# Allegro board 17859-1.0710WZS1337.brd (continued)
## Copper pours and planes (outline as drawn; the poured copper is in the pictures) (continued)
3D3V_S5_KBC on L3: 27.96,55.15 28.49,55.15 28.67,54.97 28.67,54.64 28.38,54.35 28.38,51.83 27.44,50.89 27.21,50.89 26.82,51.29 26.82,53.06 27.71,53.95 27.71,54.89
3D3V_S5_PCH on TOP: 145.99,77.63 145.79,77.83 145.79,79.94 145.82,79.96 146.91,79.96 147.14,79.73 147.14,78.29 146.48,77.63
3D3V_S5_PCH on TOP: 144.37,71.58 143.68,72.27 137.87,72.27 137.85,72.28 137.29,72.28 136.7,72.88 136.7,73.54 136.95,73.79 137.81,73.79 138.02,73.59 141.65,73.59 142.21,73.03 143.99,73.03 144.16,72.85 145.61,72.85 145.79,72.67 145.79,71.73 145.64,71.58
3D3V_S5_PCH on BOTTOM: 134.72,70.18 134.69,70.21 134.69,70.92 134.82,71.05 134.82,73.79 134.89,73.87 135.71,73.87 136.06,74.22 136.06,74.37 136.11,74.42 136.57,74.42 136.62,74.37 136.62,73.79 136.75,73.66 137.36,73.66 137.41,73.61 137.41,73.31 137.23,73.13 136.27,73.13 135.99,72.85 135.99,70.67 135.5,70.18 ; 1 cut-out
3D3V_SPIVCC1 on TOP: 187.83,35.33 187.67,35.49 187.67,37.65 187.55,37.77 186.43,37.77 186.2,37.54 184.65,37.54 184.58,37.62 184.58,39.04 184.73,39.19 188.74,39.19 188.75,39.18 189.19,39.18 189.38,38.99 189.38,37.72 189.22,37.57 188.79,37.57 188.72,37.49 188.72,36.91 188.69,36.88 188.69,35.69 188.34,35.33 ; 3 cut-outs
3D3V_SSD on TOP: 216.2,18.57 216.05,18.72 216.05,21.9 216.45,22.3 221.25,22.3 221.43,22.13 221.43,18.82 221.18,18.57 ; 6 cut-outs
3D3V_SSD on TOP: 217.01,2.92 215.39,4.55 215.39,7.01 215.61,7.24 217.85,7.24 218.21,6.89 218.21,5.62 218.48,5.34 219.35,5.34 219.58,5.11 219.58,3.25 219.25,2.92 ; 5 cut-outs
3D3V_SSD on BOTTOM: 216.99,2.95 216.02,3.91 216.02,5.31 216.07,5.36 217.77,5.36 218.59,6.17 218.59,6.63 219.32,7.37 219.32,16.82 218.1,18.04 216.1,18.04 216.02,18.11 216.02,19.81 216.05,19.84 217.82,19.84 218.03,20.04 218.03,21.41 217.88,21.57 216.1,21.57 216.02,21.64 216.02,22.66 216.1,22.74 221.38,22.74 222.78,21.34 222.78,7.11 222.02,6.35 222.02,4.32 220.64,2.95
3D3V_TP_VDD on TOP: 176.17,3.89 175.58,4.47 175.58,8.13 175.64,8.18 176.88,8.18 176.96,8.11 176.96,7.11 177.26,6.81 177.26,5.62 177.46,5.41 179.27,5.41 179.65,5.79 179.65,7.29 179.55,7.39 178.45,7.39 178.2,7.65 178.2,9.3 178.38,9.48 180.89,9.48 180.97,9.4 180.97,8.49 180.89,8.41 180.33,8.41 180.21,8.28 180.21,7.52 180.41,7.32 181.12,7.32 181.38,7.06 181.38,4.68 180.59,3.89 ; 7 cut-outs
3D3V_TPAN_VDD on TOP: 57.75,90.02 57.42,90.35 57.42,92.83 57.55,92.96 61.58,92.96 61.76,92.77 61.77,92.77 61.77,90.25 61.54,90.02 ; 4 cut-outs
3D3V_VCCPRIM on TOP: 118.13,70.59 118.13,71.96 118.23,72.06 118.59,72.06 118.66,71.99 118.66,71.53 118.99,71.2 120.09,71.2 120.75,70.54 121.89,70.54 122.02,70.67 122.02,71.02 122.68,71.68 122.68,72.82 122.45,73.05 122.45,73.69 122.16,73.98 121.34,73.98 121.23,74.09 121.23,74.42 121.38,74.58 124.02,74.58 124.12,74.48 124.12,74.02 123.23,73.13 123.23,72.29 123.36,72.16 123.74,72.16 123.92,71.99 123.92,70.36 123.26,69.7 119.5,69.7 119.42,69.78 119.42,70.31 119.25,70.49 118.23,70.49 ; 2 cut-outs
3D3V_VCCPRIM on TOP: 145.66,81.71 145.59,81.79 145.59,86.18 145.46,86.31 145.46,88.72 145.71,88.98 146.48,88.98 146.6,88.85 146.6,87.71 147.36,86.95 147.36,82.48 147.52,82.32 147.52,81.87 147.36,81.71 ; 9 cut-outs
3D3V_VCCPRIM on BOTTOM: 122.4,70.26 122.3,70.36 122.3,71.25 122.55,71.5 123.97,71.5 124.07,71.4 124.07,70.39 123.95,70.26
3D3V_VCCPRIM on L3: 130.18,68.85 130.5,68.53 135.33,68.53 136.47,67.39 142.79,67.39 144.11,66.07 146.43,66.07 146.58,65.92 146.58,64.42 146.12,63.96 142.62,63.96 141.85,64.72 133.57,64.72 132.58,63.73 129.46,63.73 127.45,65.74 127.45,67.01 126.69,67.77 126.69,68.38 126.52,68.54 123.27,68.54 122.31,69.51 119.73,69.51 119.42,69.81 119.42,70.23 119.25,70.41 118.36,70.41 118.05,70.72 118.05,71.96 118.13,72.04 118.56,72.04 118.64,71.96 118.64,71.63 118.82,71.45 119.96,71.45 120.82,70.59 121.91,70.59 122.78,71.45 128.42,71.45 130.18,69.69
3D3V_WLAN on TOP: 213.15,49.35 212.01,50.5 212.01,53.55 212.52,54.05 212.52,55.45 212.64,55.58 213.02,55.58 214.01,54.59 214.8,54.59 214.93,54.46 214.93,52.17 214.7,51.95 214.14,51.95 213.68,51.49 213.68,49.43 213.61,49.35 ; 5 cut-outs
3D3V_WLAN on BOTTOM: 202.84,48.59 202.2,49.23 201.85,49.23 201.35,48.73 200.95,48.73 199.69,49.99 196.34,49.99 194.66,51.67 194.66,54.31 194.91,54.56 195.55,54.56 195.6,54.51 195.6,52.89 195.65,52.83 195.75,52.83 195.8,52.89 195.8,54.51 195.85,54.56 196.06,54.56 196.16,54.46 196.16,52.71 196.36,52.5 199.71,52.5 200.35,51.87 203.85,51.87 204.46,51.26 206.57,51.26 207.66,52.35 208.78,52.35 209.37,51.77 211.83,51.77 212.8,52.73 212.8,54.49 212.82,54.51 213.05,54.51 213.1,54.46 213.1,52.91 213.15,52.86 213.28,52.86 213.3,52.89 213.3,54.46 213.35,54.51 213.79,54.51 214.55,53.75 214.55,52.12 212.52,50.09 207.77,50.09 206.27,48.59
+DC_IN on TOP: 31.64,86.79 31.54,86.9 31.54,87.99 31.19,88.34 30.52,88.34 30.47,88.29 29.2,88.29 29.05,88.45 29.05,88.93 28.85,89.13 27.96,89.13 27.78,89.31 27.78,90.33 27.88,90.43 32.23,90.43 33.62,89.03 35,89.03 35.2,88.83 35.2,87.12 34.87,86.79 ; 3 cut-outs
+DC_IN_C on TOP: 28.26,90.73 28.24,90.76 28.24,94.39 28.62,94.77 32.4,94.77 32.91,94.26 32.91,91.8 32.61,91.49 32.61,90.99 32.35,90.73 ; 3 cut-outs
+DC_IN_C on BOTTOM: 29.69,86.72 29.64,86.77 29.64,87.76 29.51,87.89 28.49,87.89 28.39,87.99 28.39,92.56 28.75,92.92 32.05,92.92 32.28,92.69 32.28,89.13 32.05,88.9 32.05,86.9 31.87,86.72 ; 1 cut-out
+SDC_IN on TOP: 24.58,84.58 24.48,84.69 24.48,86.26 24.56,86.34 25.19,86.34 25.29,86.44 25.29,87.56 25.11,87.73 21.66,87.73 21.53,87.86 21.53,88.34 21.42,88.46 19.39,88.46 18.99,88.85 16.81,88.85 15.95,87.99 15.95,87.15 15.69,86.9 14.8,86.9 14.65,86.74 13.81,86.74 13.63,86.92 13.63,87.61 14.78,88.75 14.78,90.88 16.02,92.13 16.33,92.13 16.63,92.43 16.63,93.2 16.89,93.45 19.48,93.45 19.98,92.94 22.42,92.94 22.93,92.43 22.93,92.13 23.79,91.26 26.05,91.26 27.55,89.77 27.55,87.07 27.1,86.62 27.1,84.71 26.97,84.58 ; 2 cut-outs
+SDC_IN on BOTTOM: 149.14,13.16 148.89,13.41 148.89,16.59 148.63,16.84 148.63,17.35 148.83,17.54 151.64,17.54 151.75,17.44 151.75,14.82 151.1,14.18 151.1,13.29 150.97,13.16
+SDC_IN on BOTTOM: 24.96,84.61 24.73,84.84 24.73,86.69 25.72,87.68 26.69,87.68 26.89,87.48 26.89,87.1 26.31,86.52 26.31,84.89 26.03,84.61 ; 2 cut-outs
+SDC_IN on L3: 25.44,27.54 28.9,27.54 29.36,27.08 29.36,23.19 29.34,23.18 32,20.53 32,20.5 32.15,20.35 36.7,20.35 39.75,17.3 39.75,14.86 38.27,13.39 31.95,13.39 28.7,16.64 28.7,19.54 25.89,22.34 25.89,23.03 25.17,23.75 24.58,23.75 23.65,24.68 23.57,24.68 21.62,26.62 13.63,26.62 13.38,26.88 13.38,38.64 13.05,38.97 13.05,54.43 14.55,55.93 14.55,61.42 13.89,62.08 13.89,65.89 12.72,67.06 12.72,80.72 13.43,81.44 13.43,82.68 13.84,83.09 13.84,83.98 13.1,84.71 13.1,91.16 13.66,91.72 16.25,91.72 16.89,92.36 16.89,93.27 17.09,93.47 18.33,93.47 18.89,92.92 18.89,91.09 18.08,90.27 18.08,89.23 17.29,88.45 17.29,86.62 17.11,86.44 17.11,79.73 16.12,78.74 16.12,74.78 17.98,72.93 17.98,65.74 18.59,65.13 18.59,53.06 17.65,52.12 17.65,42.14 17.14,41.63 17.14,40.44 18.46,39.12 18.46,35.05 21,32.51 21,30.69 21.23,30.46 22.52,30.46 ; 3 cut-outs
+SDC_IN on L4: 39.67,17.33 45.49,17.33 47.52,15.29 47.52,6.12 49.8,3.84 50.51,3.84 51.38,4.7 57.19,4.7 57.68,5.18 59.25,5.18 60.6,3.84 93.57,3.84 95.5,5.77 95.5,7.27 95.88,7.65 97.83,7.65 98.11,7.37 98.11,3.71 95.63,1.22 47.42,1.22 44.75,3.89 44.75,10.11 43.81,11.05 41.47,11.05 37.46,15.06 37.46,18.04 37.71,18.29 38.7,18.29
+SDC_IN on L4: 19.5,93.09 20.95,93.09 21.94,94.08 25.55,94.08 26.89,92.74 26.89,85.73 26.46,85.3 24.51,85.3 22.92,86.88 22.92,88.05 21.46,89.51 21.46,91.21 21.08,91.6 18.23,91.6 18,91.82 18,93.32 18.13,93.45 19.15,93.45
+SDC_IN on L6: 146.7,17.88 150.79,17.88 151.61,17.07 151.61,17.05 152.01,16.64 152.01,14.96 151.35,14.3 139.9,14.3 139.49,13.9 128.19,13.9 126.54,12.25 98.57,12.25 98.57,12.19 96.64,10.26 96.64,6.35 96.36,6.07 95.78,6.07 91.76,10.09 81.1,10.09 80.21,10.98 75.34,10.98 74.47,11.85 72.6,11.85 72.03,11.28 65.58,11.28 64.48,12.37 62.17,12.37 60.24,14.3 58.92,14.3 58.34,13.72 56.86,13.72 56.33,14.25 56.33,18.95 55.81,19.47 32.03,19.47 28.28,23.22 28.28,25.35 27.93,25.7 27.93,27.36 28.16,27.59 28.95,27.59 29.08,27.46 29.08,25.94 29.38,25.63 29.38,23.68 32.56,20.5 58.67,20.5 60.22,18.95 60.22,17.05 61.03,16.23 68.83,16.23 69.18,16.59 75.89,16.59 75.91,16.61 76.35,16.18 88.28,16.18 89.17,17.07 96.49,17.07 97.05,17.63 126.44,17.63 127.04,17.02 137.59,17.02 138.63,18.06 146.53,18.06
AD+ on TOP: 33.5,82.53 32.61,83.42 27.76,83.42 27.6,83.57 27.6,86.69 27.71,86.79 30.02,86.79 30.55,86.26 33.52,86.26 33.78,86.52 35.33,86.52 35.58,86.26 38.12,86.26 38.2,86.34 39.31,86.34 39.39,86.26 39.39,83.47 39.29,83.37 38.81,83.37 37.97,82.53 ; 6 cut-outs
AD_OFF_R on TOP: 30.37,86.79 30.19,86.97 27.98,86.97 27.68,87.28 27.68,88.72 27.78,88.83 28.7,88.83 28.85,88.67 28.85,88.27 28.98,88.14 30.52,88.14 30.6,88.22 31.06,88.22 31.29,87.99 31.29,86.85 31.24,86.79
AUD_AGND on L2GND: outline of 91 points within 1.37,0.51 26.98,24.07
AUD_AGND on L7GND: outline of 92 points within 1.37,0.51 26.98,24.07
AUD_RING on TOP: 14.7,3.48 14.52,3.66 14.52,4.52 14.62,4.63 15.26,4.63 15.49,4.4 16.2,4.4 16.44,4.16 16.44,3.67 16.25,3.48
AUD_RING on L3: 21.79,20.7 22.85,19.64 24.61,19.64 24.78,19.81 25.5,19.81 25.65,19.66 25.65,18.21 25.5,18.06 19.76,18.06 18.28,19.54 17.16,19.54 16.68,20.02 16.68,21.16 17.05,21.53 18.32,21.53 19.15,20.7
AUD_RING on L6: 18.36,19.66 17.96,19.27 17.96,18.18 16.81,17.02 16.81,16.21 16.45,15.85 16.45,14.68 16,14.23 16,11.97 16.02,11.94 16.02,11.89 14.6,10.47 14.6,7.27 14.19,6.86 14.19,6.38 14.68,5.9 14.68,4.68 15.06,4.3 16.2,4.3 16.4,4.09 16.4,3.69 15.89,3.18 15.89,3.08 13.96,3.08 13.46,3.58 13.46,5.26 13.08,5.64 13.08,11.41 15.01,13.34 15.01,15.01 15.28,15.29 15.28,15.83 15.13,15.98 15.13,16.54 15.62,17.02 15.79,17.02 16.66,17.88 16.66,20.96 16.96,21.26 17.67,21.26 18.36,20.58
AUD_SLEEVE on BOTTOM: 14.68,11.28 14.4,11.56 14.4,12.37 15.01,12.98 15.01,14.2 15.21,14.4 16.48,14.4 16.63,14.25 16.63,13.77 16.4,13.54 16.4,11.76 15.92,11.28 ; 3 cut-outs
AUD_SLEEVE on BOTTOM: 15.87,18.42 15.26,19.03 15.26,19.66 15.39,19.79 15.97,19.79 16.55,19.21 17.32,19.21 17.37,19.15 17.37,18.62 17.16,18.42
AUD_SLEEVE on L3: 15.28,19.76 15.41,19.89 16.1,19.89 17.14,18.85 17.14,16.44 16.5,15.8 16.5,14.53 16.66,14.38 16.66,13.67 16.48,13.49 15.92,13.49 15.65,13.76 15.65,16.96 16.17,17.48 16.17,17.99 15.28,18.87
AUD_SLEEVE on L4: 16.5,19.84 17.77,21.11 19.27,21.11 19.73,21.57 24.96,21.57 25.29,21.24 25.29,19.31 24.33,19.31 24,19.64 19.83,19.64 19.4,19.21 18.79,19.21 18.03,18.44 15.69,18.44 15.36,18.77 15.36,19.66 15.54,19.84 15.69,19.84 15.7,19.83 16.48,19.83 16.49,19.84
AUD_SPK_L+ on TOP: 22.3,3.33 22.17,3.46 22.17,3.94 22.27,4.04 22.27,5.18 21.81,5.64 21.81,6.28 21.91,6.38 22.88,6.38 22.93,6.33 22.93,3.53 22.73,3.33
AUD_SPK_L- on TOP: 23.57,3.38 23.06,3.89 23.06,5.39 23.41,5.74 23.41,6.25 23.54,6.38 24.45,6.38 24.56,6.28 24.56,5.64 24.3,5.39 23.95,5.39 23.64,5.08 23.64,4.5 24.2,3.94 24.2,3.53 24.05,3.38
AUD_SPK_R+ on TOP: 26.77,3.46 26.47,3.75 26.47,3.95 26.08,4.35 26.08,5.44 26.33,5.69 26.33,6.35 26.38,6.4 27.35,6.4 27.48,6.28 27.48,5.62 27.27,5.41 26.89,5.41 26.71,5.24 26.71,4.7 27.43,3.99 27.43,3.63 27.25,3.46
AUD_SPK_R- on TOP: 25.55,3.41 25.22,3.74 25.22,5.26 24.89,5.59 24.89,6.28 24.96,6.35 25.8,6.35 25.9,6.25 25.9,5.51 25.85,5.46 25.85,4.4 26.11,4.14 26.11,3.53 25.98,3.41
BT+ on TOP: 120.19,5.16 119.42,5.92 119.42,11.76 118.41,12.78 118.41,14.68 119.07,15.34 123.08,15.34 123.49,14.94 123.49,13.79 122.85,13.16 122.85,9.63 123.77,8.71 127.04,8.71 127.17,8.59 127.17,5.67 126.66,5.16 ; 5 cut-outs
BT+ on BOTTOM: 120.82,13.54 120.06,14.3 120.06,15.19 120.34,15.47 122.04,15.47 122.24,15.67 122.24,17.78 122.45,17.99 125.9,17.99 126.03,17.86 126.03,15.32 124.25,13.54
DCBATOUT on TOP: 128.49,104.42 128.34,104.57 128.34,104.93 127.93,105.34 123.84,105.34 123.54,105.64 122.37,105.64 122.07,105.34 120.34,105.34 120.09,105.59 120.09,106.28 120.72,106.91 126.66,106.91 127.65,107.9 133.95,107.9 134.08,107.77 134.08,105.57 133.78,105.26 133.78,104.5 133.7,104.42 ; 8 cut-outs
DCBATOUT on TOP: outline of 93 points within 50.71,1.68 153.16,18.09 ; 19 cut-outs
DCBATOUT on TOP: 127.2,91.44 125.83,92.81 125.83,94.64 125.98,94.8 128.26,94.8 128.57,94.49 133.67,94.49 133.69,94.48 134.65,94.48 134.72,94.41 134.72,93.86 134.53,93.67 133.74,93.67 133.42,93.35 133.42,92.43 132.43,91.44 ; 2 cut-outs
DCBATOUT on TOP: 44.7,58.4 44.62,58.47 44.62,59.18 43.99,59.82 43.99,63.45 44.37,63.83 44.37,66.42 44.65,66.7 44.65,68.61 43.22,70.03 43.22,76.56 43.4,76.74 43.4,77.6 44.29,78.49 44.29,79.56 43.89,79.96 43.89,85.12 42.39,86.62 42.39,89.46 41.27,90.58 41.27,92.28 42.59,93.6 42.59,95.33 41.83,96.09 41.83,99.26 42.89,100.33 62.65,100.33 65.24,102.91 66.42,102.91 66.45,102.95 68.92,102.95 69.44,102.43 69.44,101.91 68.93,101.4 68.93,100.99 68.83,100.89 68.83,100.49 68.37,100.03 66.16,100.03 64.01,97.87 48.74,97.87 48.61,98 46.45,98 46.27,97.82 46.27,96.73 47.31,95.68 47.33,95.68 47.33,91.77 48.03,91.07 48.03,81.77 49.42,80.37 49.42,76.53 49.32,76.43 47.29,76.43 46.58,77.14 45.84,77.14 44.8,76.1 44.8,70.13 47.16,67.77 47.16,60.43 47.44,60.15 47.44,58.8 47.29,58.65 46.93,58.65 46.68,58.4 ; 9 cut-outs
DCBATOUT on TOP: 176.88,62.64 176.88,61.45 177.39,60.94 177.39,59.46 177.83,59.02 177.83,57.44 178.16,57.11 178.16,54.5 178.05,54.38 178.05,50.47 178,50.42 177.87,50.42 177.54,50.09 177.54,48.49 178.96,47.07 178.96,44.68 181.91,41.73 189.3,41.73 189.78,42.22 192.37,42.22 192.91,42.75 195.65,42.75 195.89,42.51 195.9,42.51 195.99,42.42 200.15,42.42 200.4,42.17 200.4,41.48 199.87,40.95 197.33,40.95 196.21,39.83 183.76,39.83 182.92,38.99 182.92,37.52 185.19,35.26 185.19,34.39 187.7,31.88 187.7,28.43 187.22,27.94 183.97,27.94 183.53,27.51 183.53,25.91 183.33,25.71 181.05,25.71 179.75,27 179.75,29.21 178.4,30.56 178.4,31.45 177.74,32.11 177.41,32.11 172.31,37.21 172.31,57.23 168.6,60.94 168.6,61.8 170.1,63.3 170.1,65.89 167.02,68.96 163.27,68.96 162.86,68.56 158.08,68.56 157.98,68.66 157.98,71.2 158.34,71.55 161.18,71.55 161.56,71.94 167.66,71.94 168.65,70.94 169.92,70.94 170.45,70.41 175,70.41 175.48,69.93 175.48,64.04 ; 7 cut-outs
DCBATOUT on BOTTOM: 56.97,1.48 56.89,1.55 56.89,2.01 56.94,2.06 57.53,2.06 57.73,2.26 60.14,2.26 61.64,3.76 61.64,7.19 61.89,7.44 63.54,7.44 63.67,7.32 63.67,5.67 65.2,4.14 94.41,4.14 96.95,6.68 96.95,7.57 100.25,10.87 103.17,10.87 103.55,10.49 112.19,10.49 116.82,5.86 116.82,3.06 116.44,2.68 115.55,2.68 109.65,8.59 102.53,8.59 100.76,6.81 100.76,5.41 96.82,1.48
DCBATOUT on BOTTOM: 127.83,91.52 126.03,93.32 124.23,93.32 123.98,93.56 123.98,94.86 124.05,94.92 124.84,94.92 124.96,94.8 128.21,94.8 128.54,94.47 133.7,94.47 133.78,94.39 133.78,93.75 133.67,93.65 132.38,93.65 132.15,93.42 132.15,92.59 132.68,92.05 132.68,91.75 132.46,91.52 ; 5 cut-outs
DCBATOUT on BOTTOM: 128.59,104.42 128.49,104.52 128.49,104.55 127.4,105.64 122.09,105.64 121.2,104.75 119.35,104.75 119.04,104.45 115.59,104.45 115.44,104.6 115.44,104.83 115.82,105.21 116.43,105.21 116.71,105.49 116.71,106.33 116.35,106.68 116.35,107.14 116.58,107.37 117.01,107.37 118.5,105.88 119.06,105.88 120.16,106.99 125.88,106.99 125.93,107.04 126.89,107.04 127.6,107.75 133.29,107.75 133.42,107.62 133.42,105.51 133.78,105.16 133.78,104.5 133.7,104.42 ; 5 cut-outs
DCBATOUT on BOTTOM: 84.94,97.49 84.69,97.74 84.69,98.4 84.94,98.65 84.94,99.54 85.15,99.75 86.38,99.75 86.63,99.49 86.63,97.61 86.51,97.49 ; 2 cut-outs
DCBATOUT on BOTTOM: 58.13,6.99 58.01,7.11 58.01,9.43 58.11,9.53 59.3,9.53 59.56,9.27 59.56,8.11 59.43,7.98 59.43,7.24 59.18,6.99
DCBATOUT on BOTTOM: 47.17,76.61 47.17,76.78 46.84,77.11 46.37,77.11 46.31,77.17 46.31,77.66 46.73,78.08 46.73,79.05 46.96,79.28 49.22,79.28 49.42,79.07 49.42,76.71 49.09,76.38 47.4,76.38 ; 2 cut-outs
DCBATOUT on BOTTOM: 128.95,11.38 128.82,11.51 128.82,14.43 129.08,14.68 134.61,14.68 135.25,15.32 137.46,15.32 139.16,17.02 142.49,17.02 142.72,16.79 142.72,14.3 142.46,14.05 140.1,14.05 139.47,13.41 136.82,13.41 134.79,11.38 ; 5 cut-outs
DCBATOUT on BOTTOM: 45.36,58.65 44.65,59.36 43.83,59.36 43.73,59.46 43.73,60.02 43.43,60.33 43.43,60.66 43.48,60.71 43.96,60.71 44.04,60.63 44.72,60.63 44.95,60.4 48.28,60.4 48.38,60.51 48.38,62.66 48.58,62.87 49.17,62.87 49.68,63.38 50.16,63.38 50.24,63.3 50.24,59.62 49.27,58.65 ; 4 cut-outs
DCBATOUT on L6: outline of 84 points within 66.92,68.28 172.49,108.44 ; 20 cut-outs
DCBATOUT on L6: 115.74,3 115.36,3.38 115.36,7.7 113.33,9.73 101.39,9.73 101.01,10.11 101.01,11.25 101.39,11.64 109.14,11.64 109.52,11.25 110.28,11.25 110.66,11.64 116.12,11.64 119.17,8.59 123.36,8.59 128.45,13.68 128.81,13.68 128.98,13.85 139.88,13.85 140.56,12.83 141.24,13.85 141.55,13.85 142.11,12.63 142.66,13.85 153.33,13.85 155.44,15.95 163.77,15.95 164.54,16.72 168.47,16.72 169.11,17.35 178.1,17.35 178.86,18.11 178.86,18.75 178.63,18.98 178.63,20.37 179.24,20.98 179.24,26.37 180.41,27.54 183.38,27.54 183.53,27.38 183.53,26.11 183.71,25.94 189.4,25.94 191.18,24.16 191.18,20.65 187.33,16.8 187.33,15.33 185.87,13.87 184.4,13.87 183.9,13.38 183.9,10.99 183.41,10.49 183.41,8.51 179.78,4.88 149.22,4.88 148.79,4.45 127.86,4.45 126.41,3 ; 7 cut-outs
DCBATOUT on L6: 58.72,9.35 62.02,9.35 63.67,7.7 63.67,6.94 63.29,6.56 59.23,6.56 58.59,7.19 58.59,9.22
DCBATOUT_LCD on TOP: 37.1,90.91 37,91.01 37,92.66 37.19,92.85 37.78,92.85 37.87,92.94 37.87,97.41 38.32,97.87 40.99,97.87 41.12,97.74 41.12,92.18 40.96,92.03 39.72,92.03 38.6,90.91 ; 2 cut-outs
DCBATOUT_LCD on BOTTOM: 37.94,91.7 37.89,91.75 37.89,92.64 38.2,92.94 38.2,93.58 38.32,93.7 39.67,93.7 39.82,93.55 39.82,92.94 39.67,92.79 38.81,92.79 38.73,92.71 38.73,91.75 38.68,91.7
EC_AGND on TOP: 39.31,28.93 39.24,29.01 39.24,30.28 39.06,30.46 38.88,30.46 38.55,30.79 38.55,32.13 40.08,32.13 40.28,32.34 41.19,32.34 41.35,32.18 41.35,31.78 40.41,30.84 40.05,30.84 39.85,30.64 39.85,29.01 39.77,28.93 ; 2 cut-outs
FBA_PLL_AVDD on TOP: 188.69,80.29 188.49,80.5 188.49,80.9 188.49,81.61 188.49,81.61 188.49,82.33 188.54,82.37 189.25,82.37 189.89,83.01 190.27,83.01 190.39,82.88 190.39,82.5 189.63,81.74 189.63,80.52 189.4,80.29 ; 2 cut-outs
FBA_PLL_AVDD on TOP: 187.09,88.09 186.08,89.11 186.08,89.36 185.7,89.74 184.98,89.74 183.61,91.11 183.61,91.34 184.13,91.86 184.49,91.86 187.85,88.5 187.85,88.22 187.73,88.09 ; 2 cut-outs
GPU_I2C on BOTTOM: 188.51,57.23 188.39,57.36 188.39,58.63 188.51,58.75 188.51,60.4 188.64,60.53 191.31,60.53 191.43,60.4 191.43,59.39 190.75,58.7 189.73,58.7 189.27,58.24 189.27,57.36 189.15,57.23 ; 2 cut-outs
HDMI_PLL_GND on TOP: 20.09,52.53 19.78,52.83 18.61,52.83 17.18,54.27 17.18,56.66 16.15,57.69 16.15,63.22 16.5,63.58 17.32,63.58 17.37,63.53 17.37,58.75 18.74,57.38 18.74,55.3 19.3,54.74 22.73,54.74 22.85,54.61 22.85,53.67 21.71,52.53 ; 1 cut-out
JGND on TOP: 27.05,90.55 26.16,91.44 23.9,91.44 23.29,92.05 23.29,95.33 23.41,95.46 24.84,95.46 25.06,95.23 25.06,94.59 25.89,93.77 27.57,93.77 27.98,93.35 27.98,90.73 27.81,90.55 ; 3 cut-outs
JGND on BOTTOM: 23.92,87.76 22.45,89.23 22.45,90.86 21.79,91.52 20.75,91.52 20.64,91.62 20.64,93.17 20.77,93.3 21.51,93.3 21.86,92.94 23.21,92.94 23.95,93.68 25.83,93.68 26.21,93.3 26.21,89.36 26.41,89.16 27.58,89.16 27.88,88.85 27.88,87.89 27.76,87.76 ; 1 cut-out
PEX_PLLVDD on TOP: 177.36,91.98 176.22,93.12 176.22,93.3 177.18,94.26 177.54,94.26 178.04,93.77 178.37,93.77 179.55,94.95 179.72,94.95 180.12,94.55 180.12,94.33 180.13,94.31 178.92,93.11 178.64,93.11 177.51,91.98 ; 2 cut-outs
PEX_PLLVDD on BOTTOM: 179.42,104.12 179.34,104.19 179.34,105.39 179.72,105.77 180.08,105.77 180.18,105.67 180.18,104.22 180.08,104.12
PEX_PLLVDD on L6: 180.72,89.08 180.21,88.57 179.5,88.57 178.35,89.72 178.35,96.12 178.56,96.32 179.27,96.32 180.72,94.87
PEX_SVDD on BOTTOM: 176.47,95.15 176.19,95.43 176.19,96.34 176.24,96.4 177.06,96.4 177.26,96.6 177.26,97.56 177.41,97.72 178.33,97.72 178.58,97.97 178.58,98.76 178.71,98.88 179.65,98.88 179.75,98.78 179.75,97.74 177.16,95.15 ; 1 cut-out
PWR_1D0V_PH on BOTTOM: 148.08,62.97 147.82,63.22 147.82,68.02 147.95,68.15 148.76,68.15 148.84,68.23 148.84,68.74 148.89,68.79 152.29,68.79 152.47,68.61 152.47,67.95 152.37,67.85 149.8,67.85 149.65,67.69 149.65,66.27 149.93,65.99 152.17,65.99 152.47,65.69 152.47,63.45 151.99,62.97
PWR_1D35V_BOOT on BOTTOM: 182.77,50.24 182.7,50.32 182.7,52.78 182.75,52.83 183,52.83 183.74,52.1 183.74,50.32 183.66,50.24
PWR_1D35V_LDO_P5 on TOP: 185.64,55.3 185.26,55.68 185.26,56.24 185.44,56.42 185.64,56.42 185.92,56.7 185.92,56.87 186,56.95 186.89,56.95 186.96,56.87 186.96,56.24 186.4,55.68 186.4,55.4 186.3,55.3 ; 1 cut-out
PWR_1D35V_LDO_P5 on BOTTOM: 182.87,54.26 182.8,54.33 182.8,54.61 183.53,55.35 183.53,56.19 183.76,56.42 185.67,56.42 185.8,56.29 185.8,56.01 185.67,55.88 185.41,55.88 185.13,56.16 183.86,56.16 183.79,56.09 183.79,54.33 183.71,54.26
PWR_1D35V_PHASE on BOTTOM: 185.34,49.58 184.7,50.22 184.12,50.22 183.94,50.4 183.94,52.1 182.8,53.24 182.8,53.57 182.82,53.6 183.94,53.6 183.99,53.65 183.99,54.51 184.04,54.56 185.95,54.56 186,54.51 186,50.12 185.46,49.58 ; 1 cut-out
PWR_1V on BOTTOM: 154.38,84.28 153.87,84.79 150.39,84.79 150.29,84.89 150.29,87.61 150.39,87.71 154.38,87.71 154.73,87.35 154.73,84.46 154.55,84.28 ; 3 cut-outs
PWR_1V_PHASE on BOTTOM: 148.43,85.37 148.41,85.4 148.41,85.93 148.33,86.01 147.29,86.01 147.24,86.06 147.24,86.26 147.29,86.31 148.23,86.31 148.36,86.44 148.36,87.33 148.28,87.4 147.67,87.4 147.62,87.45 147.62,87.66 147.72,87.76 147.87,87.76 147.95,87.68 149.55,87.68 149.6,87.63 149.6,85.42 149.55,85.37
PWR_1V_PVDD on BOTTOM: 143.68,81.89 143.57,82.01 143.57,84.01 142.82,84.76 142.82,86.72 142.95,86.85 145.13,86.85 145.21,86.77 145.21,86.41 145.28,86.34 146.07,86.34 146.09,86.31 146.09,86.03 146.02,85.96 145.13,85.96 144.95,85.78 144.95,82.91 145.31,82.55 145.31,81.97 145.23,81.89 ; 4 cut-outs
PWR_2D5V on BOTTOM: 60.61,13.25 60.5,13.36 60.5,13.77 59.86,14.4 59.86,15.29 59.94,15.37 61.56,15.37 61.61,15.42 61.61,15.95 61.69,16.03 62.73,16.03 63.8,17.1 65.7,17.1 65.88,16.92 65.88,14.68 65.81,14.61 64.41,14.61 64.26,14.46 62.43,14.46 62.17,14.2 62.17,13.34 62.08,13.25 ; 3 cut-outs
PWR_2D5V_FB on BOTTOM: 62.53,12.83 62.4,12.96 62.4,14.1 62.45,14.15 64.21,14.15 64.36,14 65.86,14 65.91,13.95 65.91,13.39 65.86,13.34 64.51,13.34 64.07,12.89 63.41,12.89 63.34,12.83 ; 3 cut-outs
PWR_3D3V on TOP: 184.12,43.79 183.97,43.94 183.97,48.19 184.04,48.26 184.6,48.26 184.65,48.21 184.65,48.03 184.73,47.96 185.72,47.96 185.8,48.03 189.27,48.03 189.45,47.86 189.45,44.61 189.44,44.59 189.44,44.21 189.02,43.79 ; 9 cut-outs
PWR_3D3V on BOTTOM: 185.13,44.35 184.8,44.68 184.8,47.09 185.13,47.42 188.94,47.42 189.25,47.12 189.25,44.61 189,44.35
PWR_3D3V_LDO on TOP: 194.1,47.48 193.57,48.01 193.57,51.06 193.59,51.08 194.41,51.08 194.51,50.98 194.51,48.39 195.07,47.83 195.07,47.55 194.99,47.48
PWR_3D3V_PH on TOP: 190.29,43.61 190.14,43.77 190.14,48.08 190.24,48.19 192.3,48.19 193.64,46.84 195.02,46.84 195.07,46.79 195.07,46.48 194.69,46.1 194.13,46.1 192.7,44.68 191.38,44.68 191.18,44.48 191.18,43.67 191.13,43.61 ; 1 cut-out
PWR_3D3V_PH on BOTTOM: 190.67,44.25 190.52,44.4 190.52,48.01 190.7,48.19 192.3,48.19 193.19,47.3 193.19,45.14 192.3,44.25
PWR_5V on TOP: 39.29,2.87 39.03,3.13 39.03,7.95 39.29,8.21 44.24,8.21 44.75,7.7 44.75,4.02 44.37,3.63 40.56,3.63 39.8,2.87 ; 12 cut-outs
PWR_5V on BOTTOM: 39.29,2.62 38.91,3 38.91,8.59 39.03,8.71 44.11,8.71 44.75,8.08 44.75,3.76 43.61,2.62
PWR_5V_PH on BOTTOM: 46.15,3.76 45.89,4.02 45.89,7.19 46.15,7.44 51.1,7.44 52.11,6.43 52.11,6.17 51.99,6.05 51.1,6.05 50.97,5.92 50.97,5.67 49.07,3.76 ; 2 cut-outs
PWR_CHG_BOOT2 on BOTTOM: 159.68,13.41 159.3,13.79 159.3,15.32 159.43,15.45 159.43,16.08 159.56,16.21 160.45,16.21 160.57,16.08 160.57,15.45 159.81,14.68 159.81,13.92 160.06,13.67 160.06,13.54 159.94,13.41
PWR_CHG_HG1_R on TOP: 143.94,4.09 143.76,4.27 143.76,5.95 143.89,6.07 144.6,6.07 144.65,6.02 144.65,5.67 144.72,5.59 144.72,4.19 144.62,4.09
PWR_CHG_HG1_R on BOTTOM: 166.29,12.14 166.16,12.27 166.16,13.79 167.81,13.79 168.07,13.54 168.07,12.27 167.94,12.14
PWR_CHG_HG2_R on TOP: 140.15,13.19 139.92,13.41 139.36,13.41 139.24,13.54 139.24,14.05 139.36,14.18 140.89,14.18 141.4,13.67 141.4,13.26 141.32,13.19
PWR_CHG_LGATE1 on TOP: 149.04,11.71 148.71,12.04 147.54,12.04 147.49,12.09 147.49,12.78 147.75,13.03 149.02,13.03 149.52,12.52 149.52,11.92 149.32,11.71
PWR_CHG_LGATE1 on BOTTOM: 162.1,12.14 161.97,12.27 161.97,13.16 162.22,13.41 162.86,13.41 162.99,13.29 162.99,12.78 162.6,12.4 162.6,12.27 162.48,12.14
PWR_CHG_LGATE2 on TOP: 136.19,6.68 135.93,6.94 135.93,7.7 136.32,8.08 136.95,8.08 137.08,7.95 137.08,6.94 136.82,6.68
PWR_CHG_PHASE1 on TOP: 163.38,12.46 163.11,12.73 163.11,12.96 163.66,13.5 163.66,14.85 164.13,15.32 165.27,15.32 165.53,15.06 165.53,14.18 165.4,14.05 164.64,14.05 164.38,13.79 164.38,13.19 163.66,12.46
PWR_CHG_PHASE1 on TOP: 142.64,4.96 142.62,4.98 142.62,5.84 142.16,6.3 142.16,10.62 144.52,12.98 146.93,12.98 146.98,12.93 146.98,9.73 146.86,9.6 144.95,9.6 144.7,9.35 144.7,6.56 144.57,6.43 143.81,6.43 143.55,6.17 143.55,5.01 143.5,4.96
PWR_CHG_PHASE1 on BOTTOM: 142.34,6.2 142.16,6.38 142.16,10.65 144.7,13.19 148.63,13.19 148.71,13.11 148.71,9.65 148.66,9.6 145.33,9.6 145.21,9.48 145.21,6.53 144.88,6.2
PWR_CHG_PHASE2 on TOP: 137.84,6.23 137.46,6.61 137.46,10.37 137.59,10.49 138.98,10.49 139.24,10.75 139.24,13.03 139.36,13.16 139.95,13.16 140.23,12.88 141.22,12.88 141.27,12.83 141.27,11.89 141.9,11.25 141.9,6.45 141.68,6.23 ; 1 cut-out
PWR_CHG_PHASE2 on BOTTOM: 138.45,6.17 137.18,7.44 133.9,7.44 133.78,7.57 133.78,10.87 133.9,11 134.66,11 136.82,13.16 140.63,13.16 141.9,11.89 141.9,6.4 141.68,6.17
PWR_CHG_PHASE2_R on BOTTOM: 160.7,13.41 160.57,13.54 160.57,13.92 161.46,14.81 161.46,15.32 161.59,15.45 161.59,15.98 161.74,16.13 162.35,16.13 162.43,16.06 162.43,14.81 162.05,14.43 161.72,14.43 161.21,13.92 161.21,13.54 161.08,13.41
PWR_CHG_UGATE1 on BOTTOM: 163.37,11.38 163.24,11.51 163.24,12.04 164.1,12.91 164.1,13.69 164.21,13.79 165.65,13.79 165.78,13.67 165.78,12.4 165.65,12.27 164.64,12.27 163.75,11.38
PWR_CHG_UGATE2 on BOTTOM: 160.06,13.79 159.81,14.05 159.81,14.56 160.45,15.19 160.57,15.19 160.7,15.32 160.7,15.95 160.78,16.03 161.36,16.03 161.41,15.98 161.41,15.5 161.33,15.42 161.33,14.94 160.45,14.05 160.45,13.92 160.32,13.79
PWR_CHG_VBAT1 on BOTTOM: 157.09,11.76 156.89,11.97 156.53,11.97 156.33,12.17 156.33,12.78 155.82,13.29 155.19,13.29 154.96,13.52 154.96,14.2 154.78,14.38 154.63,14.38 154.53,14.48 154.53,14.96 154.6,15.04 154.98,15.04 155.14,14.89 155.14,14.46 155.32,14.28 155.44,14.28 155.81,13.91 156.6,13.91 157.51,12.99 157.51,12.33 157.88,11.97 158.46,11.97 158.54,11.89 158.54,11.81 158.49,11.76 ; 2 cut-outs
PWR_CHG_VBATIN on TOP: 118.75,3.42 118.49,3.69 118.49,4.35 118.79,4.65 126.79,4.65 127.68,5.54 127.68,7.32 127.81,7.44 128.31,7.44 129.38,6.38 133.42,6.38 133.52,6.28 133.52,3.69 133.27,3.43 120.19,3.43 120.17,3.42 ; 1 cut-out
PWR_CHG_VBATIN_R on TOP: 129.61,7.04 129.48,7.17 129.48,8.05 129.33,8.21 127.68,8.21 127.55,8.33 127.55,8.71 127.27,8.99 124.84,8.99 124.58,9.25 124.58,11.18 124.73,11.33 128.65,11.33 129.18,10.8 133.5,10.8 133.65,10.65 133.65,8.31 133.52,8.18 133.52,7.06 133.5,7.04
PWR_CHG_VBATIN_R on BOTTOM: 129.46,7.44 128.82,8.08 127.68,8.08 127.43,8.33 127.43,9.86 127.68,10.11 128.7,10.11 129.56,10.98 132.51,10.98 132.58,10.9 132.58,7.52 132.51,7.44
PWR_DCBATOUT_1D0V on TOP: 152.88,64.95 152.67,65.15 152.67,70.28 153.54,71.15 157.55,71.15 157.68,71.02 157.68,68.61 157.19,68.13 157.19,65.26 156.89,64.95 ; 2 cut-outs
PWR_DCBATOUT_1D0V on BOTTOM: 152.88,64.93 152.72,65.08 152.72,68.91 152.32,69.32 148.89,69.32 148.81,69.4 148.81,70.54 148.86,70.59 151.84,70.59 152.03,70.78 152.04,70.77 155.95,70.77 156.03,70.69 156.03,67.24 156.28,66.98 157.35,66.98 157.47,66.86 157.47,65.99 157.35,65.86 155.7,65.86 155.54,65.71 153.69,65.71 153.59,65.61 153.59,65.05 153.46,64.93 ; 2 cut-outs
PWR_DCBATOUT_1D35V on TOP: 180.89,49.99 180.64,50.24 178.48,50.24 178.33,50.4 178.33,53.42 178.4,53.5 178.73,53.5 178.94,53.29 182.54,53.29 184.07,51.77 184.07,50.12 183.94,49.99 ; 3 cut-outs
PWR_DCBATOUT_1D35V on BOTTOM: 179.24,50.24 178.99,50.5 178.99,52.4 179.24,52.66 180.77,52.66 181.27,53.16 182.29,53.16 182.54,52.91 182.54,51.51 182.29,51.26 182.29,50.37 182.16,50.24 ; 1 cut-out
PWR_DCBATOUT_3D3V on TOP: 195.96,42.73 195.73,42.95 195.73,43.94 195.88,44.1 195.88,45.11 195.73,45.27 195.45,45.27 195.32,45.39 195.32,46.26 195.37,46.31 196.59,46.31 197.38,45.52 201.29,45.52 201.39,45.42 201.39,43.67 200.45,42.73 ; 9 cut-outs
PWR_DCBATOUT_5V on TOP: 53.16,6.96 52.88,7.24 52.88,9.48 53,9.6 57.4,9.6 57.68,9.32 57.68,7.06 57.58,6.96 ; 2 cut-outs
PWR_DCBATOUT_5V on BOTTOM: 56.38,5.84 56.33,5.9 56.33,6.23 56.2,6.35 55.62,6.35 55.57,6.4 55.57,6.78 55.34,7.01 54.22,7.01 53.77,6.56 52.62,6.56 52.37,6.81 52.37,7.44 52.7,7.78 52.7,8.89 53.16,9.35 57.59,9.35 57.64,9.3 57.64,8.85 57.7,8.79 57.7,6.91 57.86,6.76 57.86,5.9 57.8,5.84 ; 3 cut-outs
PWR_DCBATOUT_VCCGTA on TOP: 52.17,75.69 51.71,76.15 50.13,76.15 49.68,76.61 49.68,80.11 49.88,80.32 50.29,80.32 51.25,81.28 52.29,81.28 52.39,81.38 52.39,82.78 52.42,82.81 53.51,82.81 53.54,82.78 53.54,75.82 53.41,75.69 ; 4 cut-outs
PWR_DCBATOUT_VCCGTA on TOP: 50.64,66.12 50.36,66.4 50.36,67.39 50.35,67.4 50.35,68.06 49.63,68.79 49.63,70.49 50.08,70.94 50.97,70.94 51.1,71.07 51.1,72.34 51.23,72.47 52.24,72.47 52.37,72.34 52.37,66.37 52.11,66.12 ; 4 cut-outs
PWR_DCBATOUT_VCCGTA on BOTTOM: 50.79,65.99 50.64,66.14 50.64,66.73 50.41,66.96 50.41,68.02 48.74,69.7 48.74,70.23 48.17,70.81 48.17,75.56 47.87,75.85 47.87,75.95 48,76.08 49.65,76.08 49.78,76.2 49.78,79.78 49.79,79.8 49.79,81.09 51.99,83.29 53.72,83.29 53.94,83.06 53.94,80.24 53.46,79.76 53.46,76.71 53.45,76.7 53.45,75.91 53.28,75.75 52.45,75.75 51.96,76.23 51.51,76.23 49.17,73.89 49.19,73.87 49.19,72.98 49.32,72.85 51.73,72.85 52.11,72.47 52.11,66.25 51.86,65.99 ; 11 cut-outs
PWR_DCBATOUT_VCCGTA on L3: 51.99,80.09 53.51,80.09 53.64,79.96 53.64,76.66 53,76.02 51.86,76.02 51.61,76.28 51.61,79.71
PWR_DCBATOUT_VCCGTA on L4: 54.2,80.44 54.53,80.11 54.53,75.42 52.37,73.26 52.37,67.72 51.33,66.68 50.03,66.68 49.5,67.21 49.5,71.99 50.16,72.65 50.16,73.89 51.84,75.57 51.84,76.08 51.35,76.56 51.35,80.14 51.66,80.44
PWR_DCBATOUT_VCCGTA on L6: 51.84,80.11 53.33,80.11 53.56,79.89 53.56,78.44 53.28,78.16 51.89,78.16 51.63,78.41 51.63,79.91
PWR_DCBATOUT_VCCSA on BOTTOM: 89.71,97.01 89.28,97.44 87.01,97.44 86.86,97.59 86.86,99.77 87.07,99.98 90.42,99.98 90.75,100.31 91.46,100.31 91.59,100.43 91.59,100.66 91.66,100.74 94,100.74 94.08,100.66 94.08,97.13 93.95,97.01 ; 2 cut-outs
PWR_DCBATOUT_VCORE on TOP: 51.2,55.7 50.57,56.34 50.57,60.73 50.74,60.91 51.48,60.91 51.73,61.17 51.73,62.31 51.86,62.44 52.75,62.44 52.88,62.31 52.88,59.64 53,59.51 53.69,59.51 53.92,59.29 53.92,55.86 53.77,55.7 ; 4 cut-outs
PWR_DCBATOUT_VCORE on BOTTOM: 50.77,55.63 50.67,55.73 50.67,62.59 50.64,62.61 50.64,63.3 50.72,63.38 51.73,63.38 52.8,62.31 52.8,60.53 54.02,59.31 54.02,55.73 53.92,55.63 ; 4 cut-outs
PWR_DCBATOUT_VDDQ on TOP: 48.03,12.55 47.85,12.73 47.85,15.01 47.29,15.57 47.29,16.31 47.34,16.36 49.55,16.36 49.88,16.03 50.84,16.03 50.95,15.93 50.95,15.6 50.79,15.45 50.49,15.45 50.44,15.4 50.44,12.83 50.16,12.55 ; 1 cut-out
PWR_DCBATOUT_VDDQ on BOTTOM: 48.48,13.03 47.9,13.62 47.9,16.36 48,16.46 49.7,16.46 49.82,16.35 49.82,14.98 50.4,14.39 52.38,14.39 52.57,14.2 52.57,13.34 52.43,13.2 51.06,13.2 50.9,13.03 ; 2 cut-outs
PWR_VCCGT_SWA on TOP: 55.42,69.93 55.04,70.31 55.04,74.25 54.78,74.5 53.77,74.5 53.51,74.75 53.51,75.29 53.74,75.52 55.32,75.52 55.82,76.02 59.86,76.02 60.24,75.64 60.24,74.63 60.12,74.5 57.96,74.5 57.45,73.99 57.45,70.06 57.32,69.93
PWR_VCCGT_SWA on BOTTOM: 56.05,69.42 55.67,69.8 55.67,75.39 56.31,76.02 57.19,76.02 57.83,76.66 57.83,77.93 58.13,78.23 59.81,78.23 59.83,78.22 60.62,78.22 60.68,78.16 60.68,76.52 60.24,76.08 60.24,69.93 59.73,69.42
PWR_VCCGT_SWB on TOP: 56.56,78.44 56.18,78.82 56.18,84.74 55.95,84.97 54.76,84.97 54.74,84.98 54.74,85.75 55,86.01 60.67,86.01 61.26,85.42 61.26,84.15 61,83.9 60.5,83.9 60.24,83.64 60.24,80.34 60.88,79.71 60.88,78.69 60.62,78.44
PWR_VCCGT_SWB on BOTTOM: 56.56,78.44 56.18,78.82 56.18,84.36 55.82,84.71 55.82,84.91 55.92,85.02 56.89,85.02 57.91,86.03 58.59,86.03 59.2,86.64 59.2,87.48 59.33,87.61 60.29,87.61 60.42,87.48 60.42,85.68 60.55,85.55 61,85.55 61.26,85.3 61.26,84.15 61,83.9 60.5,83.9 60.24,83.64 60.24,80.6 61,79.83 61,78.82 60.7,78.51 57.02,78.51 56.94,78.44
PWR_VCCSA_DRVH on BOTTOM: 89,102.11 88.39,102.72 88.39,104.17 88.49,104.27 89.33,104.27 89.35,104.24 89.35,103.25 89.91,102.69 89.91,102.26 89.76,102.11
PWR_VCCSA_DRVL on BOTTOM: 91.61,103.58 91.61,103.99 91.69,104.07 91.87,104.07 92.06,104.26 92.06,105.48 91.89,105.64 91.46,105.64 91.31,105.49 90.77,105.49 90.75,105.51 90.75,106.35 90.85,106.45 92.6,106.45 92.75,106.3 92.75,105.06 92.48,104.78 92.48,103.69 92.37,103.58
PWR_VCCSA_SW on BOTTOM: 90.24,102.82 90.01,103.05 90.01,103.46 90.32,103.76 90.57,103.76 90.75,103.94 90.75,104.27 91.31,104.27 91.36,104.22 91.36,103.41 90.77,102.82
PWR_VCCSA_SW on BOTTOM: 96.82,97.74 96.56,98 96.56,98.5 96.36,98.71 95.55,98.71 95.37,98.53 94.71,98.53 94.63,98.61 94.63,100.99 94.48,101.15 93.09,101.15 92.98,101.25 92.98,104.45 93.9,105.36 94.23,105.36 95.09,104.5 97.43,104.5 98.34,103.58 98.34,98.25 97.83,97.74
PWR_VCORE_SW on TOP: 57.07,58.37 55.8,59.64 55.8,60.53 55.54,60.78 55.54,64.34 55.29,64.59 54.27,64.59 54.15,64.72 54.15,65.15 55.49,66.5 58.85,66.5 60.37,64.98 60.37,58.75 59.99,58.37
PWR_VCORE_SW on BOTTOM: 57.19,58.37 56.18,59.39 56.18,63.96 55.54,64.59 54.53,64.59 54.27,64.85 54.27,65.28 55.49,66.5 58.72,66.5 60.12,65.1 60.12,58.5 59.99,58.37
PWR_VDDQ on TOP: 39.13,11.93 39.03,12.02 39.03,15.48 39.8,16.24 43.1,16.24 43.61,15.74 43.61,12.18 43.35,11.93 ; 6 cut-outs
PWR_VDDQ on BOTTOM: 39.03,11.04 38.78,11.29 38.78,16.5 38.91,16.62 42.72,16.62 43.73,15.61 43.73,11.42 43.35,11.04
PWR_VDDQ_PH on BOTTOM: 45.49,11.2 44.6,12.09 44.6,15.5 45.38,16.28 47.34,16.28 47.64,15.98 47.64,13.59 48.43,12.8 51.02,12.8 51.1,12.88 51.1,12.96 51.12,12.98 53.94,12.98 54.1,12.83 54.1,11.53 53.97,11.41 50.84,11.41 50.82,11.38 50.08,11.38 49.91,11.2
PWR_VDDQ_VLDOIN on TOP: 51.99,15.95 51.73,16.21 51.73,17.48 54.27,17.48 54.35,17.4 54.35,16.11 54.2,15.95 ; 1 cut-out
PWR_VDDQ_VTT on BOTTOM: 53.05,15.34 53.05,15.9 53.61,16.46 54.25,16.46 54.26,16.47 56.09,16.47 56.28,16.67 56.28,17.15 56.29,17.16 56.29,17.76 56.39,17.86 56.92,17.86 57.02,17.76 57.02,15.5 56.86,15.34 ; 2 cut-outs
PWR_VGA_CORE_BOOT2 on TOP: 120.77,96.5 120.68,96.59 120.68,97.4 120.95,97.67 120.95,98.07 120.64,98.38 120.47,98.38 120.44,98.4 120.44,99.01 120.47,99.04 120.64,99.04 121.81,97.87 121.81,96.62 121.69,96.5
PWR_VGA_CORE_PHASE1 on TOP: 120.95,100.84 120.85,100.94 120.85,101.35 121.52,102.02 121.52,102.28 121.51,102.29 121.51,102.47 121.89,102.85 121.89,103.76 122.02,103.89 122.78,103.89 123.18,104.3 123.82,104.3 123.95,104.17 123.95,103.76 122.3,102.11 122.3,101.63 122.07,101.4 122.04,101.4 121.48,100.84 ; 1 cut-out
PWR_VGA_CORE_PHASE1 on TOP: 128.62,101.02 128.49,101.15 128.49,103.84 128.57,103.91 133.75,103.91 134,104.17 134,105.06 134.92,105.97 135.86,105.97 135.93,105.9 135.93,103.13 133.83,101.02
PWR_VGA_CORE_PHASE1 on BOTTOM: 128.62,101.02 128.49,101.15 128.49,103.84 128.57,103.91 133.78,103.91 134,104.14 134,105.06 134.66,105.72 138.2,105.72 138.35,105.57 138.35,102.26 138.22,102.14 134.84,102.14 133.73,101.02
PWR_VGA_CORE_PHASE2 on TOP: 122.19,97.03 121.99,97.23 121.99,97.89 120.85,99.04 120.85,99.39 120.9,99.44 121.48,99.44 122.78,98.15 123.84,98.15 123.97,98.02 123.97,97.23 123.77,97.03 ; 2 cut-outs
PWR_VGA_CORE_PHASE2 on TOP: 128.65,94.95 128.49,95.1 128.49,97.77 128.59,97.87 135.48,97.87 135.91,97.44 135.91,95.15 135.71,94.95
PWR_VGA_CORE_PHASE2 on BOTTOM: 128.65,94.95 128.52,95.07 128.52,97.79 128.59,97.87 134.69,97.87 135.5,98.68 138.09,98.68 138.37,98.4 138.37,95.3 138.02,94.95
PWR_VGA_CORE_RGND on TOP: 115.74,95.71 115.61,95.84 115.61,99.27 115.64,99.29 115.64,99.39 115.72,99.47 118.64,99.47 118.69,99.42 118.69,99.24 118.43,98.99 117.14,98.99 116.88,98.73 116.88,98.05 117.01,97.92 117.01,97.41 117.7,96.73 117.77,96.73 117.9,96.6 117.9,96.34 117.65,96.09 116.66,96.09 116.28,95.71 ; 4 cut-outs
RING2_HPMIC1 on TOP: 12.77,2.49 12.62,2.64 12.62,4.4 12.87,4.65 13.89,4.65 14.01,4.52 14.01,2.82 13.68,2.49 ; 1 cut-out
RTC_AUX_S5 on TOP: 116.35,46.43 116.1,46.69 114.65,46.69 114.5,46.84 114.5,47.65 114.65,47.81 115.92,47.81 116.28,47.45 117.27,47.45 117.42,47.3 117.42,46.76 117.41,46.75 117.41,46.6 117.24,46.43 ; 1 cut-out
RTC_AUX_S5 on L2GND: 123.52,39.33 120.44,42.41 118.34,42.41 114.61,46.13 114.61,47.19 114.75,47.34 115.61,47.34 115.75,47.19 115.75,45.72 117.8,43.68 120.03,43.68 123.79,39.92 143.15,39.92 145.16,41.93 151.36,41.93 153.06,43.63 153.66,43.63 153.75,43.54 153.75,43.26 151.81,41.32 145.36,41.32 143.37,39.33
SLEEVE_R on BOTTOM: 12.85,11.28 12.83,11.29 12.3,11.29 11.07,12.52 3.6,12.52 3.19,12.12 2.89,12.12 2.79,12.22 2.79,13.19 2.8,13.2 2.8,13.5 3.09,13.79 11.3,13.79 11.86,13.24 14.62,13.24 14.73,13.13 14.73,12.93 14.09,12.3 14.09,11.43 13.94,11.28 ; 1 cut-out
USB_ADT on TOP: 21.48,84.13 21.34,84.27 21.34,85 20.96,85.38 20.23,85.38 19.81,85.8 19.81,87.15 20.26,87.61 20.64,87.61 20.77,87.73 20.77,88.24 20.82,88.29 21.3,88.29 21.36,88.24 21.36,87.63 21.51,87.48 23.84,87.48 23.9,87.43 23.9,84.28 23.74,84.13
USB_ADT on BOTTOM: 20.24,85.17 20.14,85.27 20.14,85.55 19.78,85.91 19.78,87.15 20.01,87.38 22.3,87.38 22.45,87.23 22.45,85.58 22.04,85.17
VGA_CORE on TOP: 141.01,93.73 140.74,94.01 140.74,107.62 140.99,107.88 147.52,107.88 148.81,106.58 151.58,106.58 151.89,106.28 151.89,105.16 151.25,104.52 147.85,104.52 147.49,104.17 147.49,102.49 147.9,102.09 151.35,102.09 151.45,101.98 151.45,94.26 150.92,93.73 ; 8 cut-outs
VGA_CORE on TOP: 174.75,73.48 168.62,79.61 168.62,79.89 168.95,80.22 171.06,80.22 172.74,81.89 177.21,81.89 180.41,78.69 180.41,76.89 178.84,75.31 176.96,75.31 175.13,73.48 ; 6 cut-outs
VGA_CORE on TOP: 184.04,82.76 182.39,84.41 182.39,84.91 180.66,86.64 180.66,86.9 180.67,87 183.16,89.49 183.28,89.49 185.57,87.2 185.82,87.2 186.46,87.84 186.58,87.84 186.97,87.45 187.22,87.45 187.47,87.71 187.73,87.71 187.85,87.58 187.85,87.33 187.47,86.95 187.22,86.95 184.68,84.41 184.68,84.28 185.19,83.77 185.19,83.64 184.3,82.76 ; 9 cut-outs
VGA_CORE on BOTTOM: 140.71,92.99 140.53,93.17 140.53,107.52 140.86,107.85 148.58,107.85 149.4,107.04 149.4,104.83 149.07,104.5 147.82,104.5 147.47,104.14 147.47,102.19 147.75,101.91 148.99,101.91 149.4,101.5 149.4,93.7 148.69,92.99
VGA_CORE on BOTTOM: 165.02,84.79 163.49,86.31 163.49,86.69 163.87,87.07 163.87,87.58 163.37,88.09 162.73,88.09 162.1,87.45 161.97,87.45 160.45,88.98 160.45,89.23 160.7,89.49 161.33,89.49 161.97,88.85 164.51,88.85 165.91,87.45 165.91,87.2 165.78,87.07 165.78,85.42 165.14,84.79 ; 4 cut-outs
VGA_CORE on BOTTOM: 179.88,72.04 178.66,73.26 178.2,73.26 178.18,73.28 175.56,73.28 175.41,73.13 175.25,73.13 174.92,73.46 174.87,73.46 168.75,79.58 168.75,79.81 170.22,81.28 171.11,81.28 171.44,80.95 172,80.95 176.8,85.75 178.91,85.75 184.25,91.09 184.6,91.09 191,84.69 191,84.13 186.58,79.71 186.51,79.71 186.36,79.56 186.36,79.12 184.63,77.4 184.63,76.66 183.18,75.21 183.18,74.63 180.59,72.04 ; 9 cut-outs
VGA_CORE on L3: 188.23,86.18 189.4,86.18 190.85,84.74 190.85,83.85 187.04,80.04 184.47,80.04 180.46,84.05 180.46,86.64 182.77,88.95 185.46,88.95
VGA_CORE on L4: 155.8,105.69 155.8,104.37 156.67,103.5 172.78,103.5 173.6,102.67 176.32,102.67 176.33,102.66 177.3,102.66 182.7,97.26 182.7,95.79 182.14,95.23 182.14,92.31 187.4,87.05 187.4,82.4 186.66,81.66 186.65,81.66 183.17,78.18 183.17,76.85 180.54,74.22 169.77,74.22 151.48,92.51 140.91,92.51 140.56,92.87 140.56,106.5 140.81,106.76 146.15,106.76 146.3,106.91 147.67,106.91 148.3,106.28 155.21,106.28
VGA_CORE on L5VCC: 179.37,73.6 178.66,74.31 171.45,74.31 165.05,80.71 163.22,80.71 151.43,92.5 147.65,92.5 146.99,93.16 140.89,93.16 140.49,93.55 140.49,106.58 140.94,107.03 148.56,107.03 149.19,106.39 155.24,106.39 155.73,105.89 155.73,104.34 157.04,103.04 159.1,103.04 159.61,103.55 169.49,103.55 169.75,103.8 174.21,103.8 175.96,102.05 177.56,102.05 183.02,96.59 183.63,96.59 183.75,96.47 183.75,95.92 183.22,95.38 183.22,92.1 183.95,91.36 183.95,89.13 185.17,87.91 185.17,87.2 187.1,85.27 187.1,82.02 182.68,77.6 182.68,76.15 180.13,73.6
N203399166 on BOTTOM: 162.05,62.21 162,62.26 162,64.57 162.83,65.41 162.83,66.22 162.12,66.93 162.12,67.64 162.22,67.74 163.85,67.74 164,67.59 164,66.73 163.42,66.14 163.42,65.2 162.71,64.49 162.71,62.23 162.68,62.21 ; 2 cut-outs

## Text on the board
Ref Des/Silkscreen Bottom: BK14 | BS14MS.VL | BK.BS15 | BS14MS | BKN14 | BKV14 | F5701:1.1A/6V | F6502:1.1A/6V | X1801:24MHZ | X7901:27MHZ | MADE IN TAIWAN | 17859-1 | TVMHG | Bucky/BenSolo WHL/CNL MB
Ref Des/Silkscreen Top: X2401:32.768KHZ | F5503:1.1A/24V | F5504:1.1A/6V | X1802:32.768KHZ
User.27: 5V_S5 | AUD_AGND | 3D3V_S5 | 5V_S0 | 1D2V_S3 | RTC_AUX_S5 | 1D0V_S5 | 1V_VCCIO | GND | 1D35V_VGA_S0 | 5V_USB2_S0
User.29: 3D3V_S5 | 5V_S5 | 1V_CPU_CORE | 1V_VCCSA | GND | VGA_CORE
User.30: AUD_AGND | 5V_S5 | GND
User.37: ByImpedance:100.0_DP@_REF_L1=("5.0/4.0(L3)" "3.0/9.0(L2)")|_REF_L6=("3.0/7.5(L5/L7)" "3.5/7.0(L4/L7)")|Type="DP"|_REF_L4=("3.0/7.5(L3/L5)" "3.5/7.0(L2/L5)")|_REF_L3=("3.5/7.0(L2/L5)" "3.0/7.5(L2/L4)")|imp="100.0"|_REF_L5=("3.5/7.0(L4/L7)")|_REF_L8=("3.0/9.0(L7)" "5.0/4.0(L6)") | ByImpedance:27.4_SE@_REF_L1=("11.0(L2)")|_REF_L6=("10.5(L5/L7)" "13.5(L4/L7)")|Type="SE"|_REF_L4=("13.5(L2/L5)" "10.5(L3/L5)")|_REF_L3=("13.5(L2/L5)" "10.5(L2/L4)")|imp="27.4"|_REF_L5=("13.5(L4/L7)")|_REF_L8=("11.0(L7)") | ByImpedance:33.0_SE@_REF_L1=("8.0(L2)")|_REF_L6=("8.1(L5/L7)" "10.0(L4/L7)")|Type="SE"|_REF_L4=("10.0(L2/L5)" "8.1(L3/L5)")|_REF_L3=("10.0(L2/L5)" "8.1(L2/L4)")|imp="33.0"|_REF_L5=("10.0(L4/L7)")|_REF_L8=("8.0(L7)") | ByImpedance:35.0_SE@_REF_L1=("7.5(L2)")|_REF_L6=("7.1(L5/L7)" "9.0(L4/L7)")|Type="SE"|_REF_L4=("9.0(L2/L5)" "7.1(L3/L5)")|_REF_L3=("9.0(L2/L5)" "7.1(L2/L4)")|imp="35.0"|_REF_L5=("9.0(L4/L7)")|_REF_L8=("7.5(L7)") | ByImpedance:37.5_SE@_REF_L1=("6.5(L2)")|_REF_L6=("8.0(L4/L7)" "6.6(L5/L7)")|Type="SE"|_REF_L4=("8.0(L2/L5)" "6.6(L3/L5)")|_REF_L3=("8.0(L2/L5)" "6.6(L2/L4)")|imp="37.5"|_REF_L5=("8.0(L4/L7)")|_REF_L8=("6.5(L7)") | ByImpedance:39.0_SE@_REF_L1=("6.0(L2)")|_REF_L6=("6.1(L5/L7)" "7.5(L4/L7)")|Type="SE"|_REF_L4=("6.1(L3/L5)" "7.5(L2/L5)")|_REF_L3=("7.5(L2/L5)" "6.1(L2/L4)")|imp="39.0"|_REF_L5=("7.5(L4/L7)")|_REF_L8=("6.0(L7)") | ByImpedance:40.0_SE@_REF_L1=("5.5(L2)")|_REF_L6=("5.6(L5/L7)" "7.0(L4/L7)")|Type="SE"|_REF_L4=("5.6(L3/L5)" "7.0(L2/L5)")|_REF_L3=("7.0(L2/L5)" "5.6(L2/L4)")|imp="40.0"|_REF_L5=("7.0(L4/L7)")|_REF_L8=("5.5(L7)") | ByImpedance:42.0_SE@_REF_L1=("5.0(L2)")|_REF_L6=("6.5(L4/L7)" "5.1(L5/L7)")|Type="SE"|_REF_L4=("5.1(L3/L5)" "6.5(L2/L5)")|_REF_L3=("6.5(L2/L5)" "5.1(L2/L4)")|imp="42.0"|_REF_L5=("6.5(L4/L7)")|_REF_L8=("5.0(L7)") | ByImpedance:45.0_SE@_REF_L1=("4.5(L2)")|_REF_L6=("5.5(L4/L7)" "4.4(L5/L7)")|Type="SE"|_REF_L4=("5.5(L2/L5)" "4.4(L3/L5)")|_REF_L3=("5.5(L2/L5)" "4.4(L2/L4)")|imp="45.0"|_REF_L5=("5.5(L4/L7)")|_REF_L8=("4.5(L7)") | ByImpedance:48.0_SE@_REF_L1=("4.0(L2)")|_REF_L6=("5.0(L4/L7)" "3.9(L5/L7)")|Type="SE"|_REF_L4=("3.9(L3/L5)" "5.0(L2/L5)")|_REF_L3=("3.9(L2/L4)" "5.0(L2/L5)")|imp="48.0"|_REF_L5=("5.0(L4/L7)")|_REF_L8=("4.0(L7)") | ByImpedance:50.0_DP@_REF_L1=("10.5/4.0(L2)")|_REF_L6=("10.5/4.0(L5/L7)" "13.0/4.0(L4/L7)")|Type="DP"|_REF_L4=("10.5/4.0(L3/L5)" "13.0/4.0(L2/L5)")|_REF_L3=("13.0/4.0(L2/L5)" "10.5/4.0(L2/L4)")|imp="50.0"|_REF_L5=("13.0/4.0(L4/L7)")|_REF_L8=("10.5/4.0(L7)") | ByImpedance:50.0_SE@_REF_L1=("3.5(L2)")|_REF_L6=("4.5(L4/L7)" "3.5(L5/L7)")|Type="SE"|_REF_L4=("3.5(L3/L5)" "4.5(L2/L5)")|_REF_L3=("3.5(L2/L4)" "4.5(L2/L5)")|imp="50.0"|_REF_L5=("4.5(L4/L7)")|_REF_L8=("3.5(L7)") | ByImpedance:55.0_SE@_REF_L6=("3.51(L4/L7)")|Type="SE"|_REF_L4=("3.51(L2/L5)")|_REF_L3=("3.51(L2/L5)")|imp="55.0"|_REF_L5=("3.51(L4/L7)") | ByImpedance:68.0_DP@_REF_L1=("6.5/5.0(L2)")|_REF_L6=("7.0/4.0(L4/L7)" "6.5/5.0(L5/L7)")|Type="DP"|_REF_L4=("7.0/4.0(L2/L5)" "6.5/5.0(L3/L5)")|_REF_L3=("6.5/5.0(L2/L4)" "7.0/4.0(L2/L5)")|imp="68.0"|_REF_L5=("7.0/4.0(L4/L7)")|_REF_L8=("6.5/5.0(L7)") | ByImpedance:70.0_DP@_REF_L1=("6.0/5.0(L2)")|_REF_L6=("6.5/4.0(L4/L7)" "6.0/5.0(L5/L7)")|Type="DP"|_REF_L4=("6.0/5.0(L3/L5)" "6.5/4.0(L2/L5)")|_REF_L3=("6.0/5.0(L2/L4)" "6.5/4.0(L2/L5)")|imp="70.0"|_REF_L5=("6.5/4.0(L4/L7)")|_REF_L8=("6.0/5.0(L7)") | ByImpedance:72.0_DP@_REF_L1=("5.5/5.0(L2)")|_REF_L6=("5.4/4.0(L5/L7)" "6.0/4.0(L4/L7)")|Type="DP"|_REF_L4=("5.4/4.0(L3/L5)" "6.0/4.0(L2/L5)")|_REF_L3=("5.4/4.0(L2/L4)" "6.0/4.0(L2/L5)")|imp="72.0"|_REF_L5=("6.0/4.0(L4/L7)")|_REF_L8=("5.5/5.0(L7)") | ByImpedance:75.0_DP@_REF_L1=("5.0/5.0(L2)")|_REF_L6=("5.0/4.0(L5/L7)" "5.5/4.0(L4/L7)")|Type="DP"|_REF_L4=("5.5/4.0(L2/L5)" "5.0/4.0(L3/L5)")|_REF_L3=("5.5/4.0(L2/L5)" "5.0/4.0(L2/L4)")|imp="75.0"|_REF_L5=("5.5/4.0(L4/L7)")|_REF_L8=("5.0/5.0(L7)") | ByImpedance:80.0_DP@_REF_L1=("5.0/7.0(L2)" "4.5/5.0(L2)")|_REF_L6=("4.4/4.5(L5/L7)" "4.5/4.0(L4/L7)")|Type="DP"|_REF_L4=("4.5/4.0(L2/L5)" "4.4/4.5(L3/L5)")|_REF_L3=("4.5/4.0(L2/L5)" "4.4/4.5(L2/L4)")|imp="80.0"|_REF_L5=("4.5/4.0(L4/L7)")|_REF_L8=("4.5/5.0(L7)" "5.0/7.0(L7)") | ByImpedance:83.0_DP@_REF_L1=("3.5/4.0(L2)")|_REF_L6=("4.0/4.5(L5/L7)" "4.5/4.5(L4/L7)")|Type="DP"|_REF_L4=("4.0/4.5(L3/L5)" "4.5/4.5(L2/L5)")|_REF_L3=("4.0/4.5(L2/L4)" "4.5/4.5(L2/L5)")|imp="83.0"|_REF_L5=("4.5/4.5(L4/L7)")|_REF_L8=("3.5/4.0(L7)") | ByImpedance:85.0_DP@_REF_L1=("9.0/4.0(L3)" "4.0/5.0(L2)")|_REF_L6=("4.0/4.0(L4/L7)" "3.5/4.0(L5/L7)")|Type="DP"|_REF_L4=("3.5/4.0(L3/L5)" "4.0/4.0(L2/L5)")|_REF_L3=("3.5/4.0(L2/L4)" "4.0/4.0(L2/L5)")|imp="85.0"|_REF_L5=("4.0/4.0(L4/L7)")|_REF_L8=("9.0/4.0(L6)" "4.0/5.0(L7)") | ByImpedance:90.0_DP@_REF_L1=("4.0/8.0(L2)" "7.5/4.0(L3)")|_REF_L6=("3.5/5.0(L5/L7)" "3.5/4.5(L4/L7)")|Type="DP"|_REF_L4=("3.5/4.5(L2/L5)" "3.5/5.0(L3/L5)")|_REF_L3=("3.5/5.0(L2/L4)" "3.5/4.5(L2/L5)")|imp="90.0"|_REF_L5=("3.5/4.5(L4/L7)")|_REF_L8=("7.5/4.0(L6)" "4.0/8.0(L7)") | ByImpedance:95.0_DP@_REF_L1=("6.0/4.0(L3)" "3.5/9.0(L2)")|_REF_L6=("3.5/8.0(L5/L7)" "3.5/5.5(L4/L7)")|Type="DP"|_REF_L4=("3.5/5.5(L2/L5)" "3.5/8.0(L3/L5)")|_REF_L3=("3.5/8.0(L2/L4)" "3.5/5.5(L2/L5)")|imp="95.0"|_REF_L5=("3.5/5.5(L4/L7)")|_REF_L8=("3.5/9.0(L7)" "6.0/4.0(L6)") | LayerIndex:nil | Source:8-1.0-15j.xls | artWorks:("_REF_L3" "_REF_L6" "_REF_L5" "_REF_L4" "_REF_L8" "_REF_L1") | gtImpOutlineUsed:BOARD GEOMETRY/PANEL_OUTLINE
User.38: Board Accuracy Check,May 30 10:04:44 2018,Passed | Dummy-Static-No Shape On Layer Check,May 30 10:04:45 2018,Passed | Split Plane Check,May 29 19:05:41 2018,Passed
User.44: This gerber is just for your reference to find the DP impedance traces in layer L1. | DP IMPEDANCE TABLE: L1 | * - Denotes that this Impedance | is NOT used | IMP(Ohm) | *50.0 | *68.0 | *70.0 | *72.0 | *75.0 | *80.0 | 80.0 | *83.0 | *85.0 | 85.0 | *90.0 | *95.0 | *100.0 | WIDTH(mils) | 10.5/4.0 | 6.5/5.0 | 6.0/5.0 | 5.5/5.0 | 5.0/5.0 | 5.0/7.0 | 4.5/5.0 | 3.5/4.0 | 9.0/4.0 | 4.0/5.0 | 4.0/8.0 | 7.5/4.0 | 6.0/4.0 | 3.5/9.0 | 5.0/4.0 | 3.0/9.0 | TYPE | DP | Ref. Plane | L2 | L3
User.45: Note:Refer to DRILL layer for ELLIPSE drill direction | FIGURE | SIZE | 10.0 | 16.0 | 20.0 | 36.0 | 103.0 | 113.0 | 115.0 | 126.0 | 150.0 | 170.0 | 178.0 | 30.0 | 44.0 | 63.0 | 86.0 | 95.0 | 40.0x20.0 | 40.0x24.0 | 44.0x20.0 | 48.0x24.0 | 62.0x28.0 | 63.0x24.0 | 63.0x36.0 | 95.0x28.0 | 134.0x95.0 | DRILL CHART: TOP to BOTTOM | ALL UNITS ARE IN MILS | PLATED | NON-PLATED | QTY | 4927 | 10 | 796 | 19 | 18 | 1 | 2 | 5 | 7 | 4 | 6 | This gerber is just for your reference to find the DP impedance traces in layer L3. | This gerber is just for your reference to find the DP impedance traces in layer L4. | This gerber is just for your reference to find the DP impedance traces in layer L5. | This gerber is just for your reference to find the DP impedance traces in layer L6. | This gerber is just for your reference to find the DP impedance traces in layer L8. | This gerber is just for your reference to find the SE impedance traces in layer L1. | This gerber is just for your reference to find the SE impedance traces in layer L3. | This gerber is just for your reference to find the SE impedance traces in layer L4. | This gerber is just for your reference to find the SE impedance traces in layer L5. | This gerber is just for your reference to find the SE impedance traces in layer L6. | This gerber is just for your reference to find the SE impedance traces in layer L8. | DP IMPEDANCE TABLE: L3 | DP IMPEDANCE TABLE: L4 | DP IMPEDANCE TABLE: L5 | DP IMPEDANCE TABLE: L6 | DP IMPEDANCE TABLE: L8 | SE IMPEDANCE TABLE: L1 | SE IMPEDANCE TABLE: L3 | SE IMPEDANCE TABLE: L4 | SE IMPEDANCE TABLE: L5 | SE IMPEDANCE TABLE: L6 | SE IMPEDANCE TABLE: L8 | * - Denotes that this Impedance | is NOT used | Model | Bucky/BenSolo WHL/CNL MB | PCB_NO | 17859 | VER. | Layer | DRILL | L1 | L2GND | L3 | L4 | TMASK | TPLACE | TSILK | TSMD | Designer | CATHY | Date | 07/10/2018 | IMP(Ohm) | *27.4 | *50.0 | *33.0 | *68.0 | *35.0 | *70.0 | *37.5 | *72.0 | *39.0 | *75.0 | *40.0 | *80.0 | 40.0 | *42.0 | *83.0 | *45.0 | *85.0 | 45.0 | 83.0 | *48.0 | *90.0 | *95.0 | 50.0 | 85.0 | *100.0 | *55.0 | 80.0 | 90.0 | WIDTH(mils) | 11.0 | 8.0 | 7.5 | 6.5 | 6.0 | 5.5 | 5.0 | 4.5 | 4.0 | 3.5 | 10.5 | 13.5 | 8.1 | 9.0 | 7.1 | 7.0 | 6.6 | 6.1 | 3.51 | 5.6 | 5.1 | 4.4 | 3.9 | 10.5/4.0 | 6.5/5.0 | 6.0/5.0 | 5.5/5.0 | 5.0/5.0 | 4.5/5.0 | 5.0/7.0 | 3.5/4.0 | 9.0/4.0 | 4.0/5.0 | 7.5/4.0 | 4.0/8.0 | 3.5/9.0 | 6.0/4.0 | 3.0/9.0 | 5.0/4.0 | 13.0/4.0 | 7.0/4.0 | 6.5/4.0 | 5.5/4.0 | 4.5/4.0 | 4.5/4.5 | 5.4/4.0 | 4.0/4.0 | 3.5/4.5 | 3.5/5.5 | 3.5/7.0 | 4.4/4.5 | 4.0/4.5 | 3.5/5.0 | 3.5/8.0 | 3.0/7.5 | TYPE | SE | DP | Ref. Plane | L2 | L7 | L2/L5 | L4/L7 | L5/L7 | L2/L4 | L3/L5 | L6 | BMASK | BPLACE | BSILK | BSMD | L5VCC | L7GND | L8
